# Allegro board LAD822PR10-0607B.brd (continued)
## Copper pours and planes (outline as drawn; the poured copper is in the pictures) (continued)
N39736574 on TOP (solid shape): 38.16,74.53 38.16,74.36 38.03,74.23 36.17,74.23 36.1,74.16 36.1,73.97 36.03,73.91 35.55,73.91 35.53,73.93 35.53,74.54 35.66,74.67 38.02,74.67
N39880453 on BOTTOM (solid shape): 114.63,111.18 114.63,110.37 114.79,110.22 115.56,110.22 115.61,110.17 115.61,109.61 115.5,109.49 113.61,109.49 113.54,109.56 113.54,111.18 113.58,111.22 114.6,111.22
N40598435 on BOTTOM (solid shape): 178.15,76.89 178.08,76.83 177.51,76.83 177.51,78.86 178.15,78.86
N40598492 on BOTTOM (solid shape): 194.59,77.97 195.23,77.97 195.67,77.53 197.01,77.53 197.07,77.46 197.07,76.58 197.01,76.51 195.86,76.51 195.23,77.15 193.89,77.15 193.58,77.46 193.58,78.23 193.67,78.32 194.25,78.32
N40598500 on BOTTOM (solid shape): 190.15,77.66 190.15,77.08 189.58,76.51 189.58,76 189.51,75.94 189,75.94 188.94,76 188.94,77.46 189.2,77.72 190.08,77.72
N40638141 on TOP (solid shape): 17.83,93.54 17.83,90.74 17.36,90.26 17.36,89.01 17.84,88.54 17.84,84.46 19.35,82.95 19.35,80.61 19.26,80.52 18.28,80.52 18.19,80.61 18.19,82.2 16.54,83.85 16.54,87.95 16.11,88.39 16.11,90.9 16.54,91.33 16.54,93.42 16.73,93.61 17.77,93.61
N40740280 on TOP (solid shape): 40.31,90.02 40.31,89.06 39.44,88.18 39.44,87.78 38.86,87.2 38.07,87.2 38.01,87.26 38.01,87.3 38,87.31 38,87.37 38.04,87.41 38.04,88.29 38.94,89.19 38.94,89.35 39.66,90.06 40.27,90.06
N40969705 on BOTTOM (solid shape): 29.35,72.42 29.35,67.94 29.19,67.77 27.17,67.77 26.91,68.03 26.91,72.45 27.13,72.66 29.11,72.66
N41096439 on TOP (solid shape): 38.4,16.41 38.4,15.01 36.99,13.59 36.99,11.1 36.5,10.61 36.5,9.66 36.41,9.57 35.67,9.57 35.59,9.65 35.59,10.62 35.8,10.83 35.8,12.14 36.07,12.14 36.07,12.08 36.09,12.03 36.11,11.98 36.13,11.94 36.17,11.89 36.2,11.86 36.25,11.83 36.3,11.8 36.35,11.79 36.4,11.78 36.45,11.78 36.51,11.79 36.56,11.8 36.61,11.83 36.65,11.86 36.69,11.89 36.72,11.94 36.75,11.98 36.77,12.03 36.78,12.08 36.78,12.14 36.78,12.19 36.77,12.24 36.75,12.29 36.72,12.34 36.69,12.38 36.65,12.42 36.61,12.45 36.56,12.47 36.51,12.48 36.45,12.49 36.4,12.49 36.35,12.48 36.3,12.47 36.25,12.45 36.2,12.42 36.17,12.38 36.13,12.34 36.11,12.29 36.09,12.24 36.07,12.19 36.07,12.14 35.8,12.14 35.8,13.77 36.79,14.76 36.79,16.4 37.08,16.7 38.11,16.7
N41548319 on TOP (solid shape): 44.07,79.17 44.07,77.12 43.81,76.86 42.41,76.86 42.28,76.98 42.28,77.15 42.46,77.33 43.08,77.33 43.4,77.66 43.4,79.22 43.45,79.27 43.97,79.27
N41864735 on BOTTOM (solid shape): 21.53,71.41 21.53,63.55 23.71,61.37 23.71,60.85 23.43,60.57 22.42,60.57 20.32,62.67 20.32,71.43 20.41,71.52 21.42,71.52

Small or netless copper shapes (teardrops, artwork), in the pictures only: 263 on TOP, 26 on BOTTOM

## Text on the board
Ref Des/Silkscreen Bottom: H6 | HNGFF | DC-IN | M2X3L | SPK | eDP | LED | KB | KB/BL | A15 | TP | BATTERY | HDD | FAN | USB | IO | SSD | DIMM 2 | DIMM 1 | ONLY FOR DDR4
User.Comments: LA-D822P | 2016-06-07 | 2017-06-07 | BKD40 | Saijuan | GNDA | GND | +5VS
COMPVAL_TYPE_TOP: LAYER | NAME | L3 | L1 | L2 | L5 | L4 | L6 | L7 | L8 | LA-D822P | TOP | GND1 | IN2 | IN3 | GND2 | IN1 | BOT | VCC | LS-XXXXP
User.39: L1-TOP | L2-GND1 | L3-IN1 | L4-VCC | L5-IN2 | L6-IN3 | L7-GND2 | L8-BOT | LAYER | NAME
User.40: FIGURE | SIZE | 8.0 | 10.0 | 22.0 | 28.0 | 30.0 | 31.0 | 35.0 | 98.0 | 110.0 | 130.0 | 142.0 | 146.0 | 157.0 | 43.0 | 63.0 | 55.0x24.0 | 63.0x24.0 | 63.0x28.0 | 63.0x35.0 | 75.0x24.0 | 94.0x28.0 | 169.0x142.0 | 189.0x165.0 | 134.0x110.0 | DRILL CHART: TOP to BOTTOM | ALL UNITS ARE IN MILS | TOLERANCE | +3.0/-3.0 | +2.0/-2.0 | PLATED | NON-PLATED | QTY | 4695 | 4 | 19 | 9 | 1 | 8 | 2 | 3 | 7
